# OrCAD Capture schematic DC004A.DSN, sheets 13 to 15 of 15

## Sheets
13 PAGE12 - LEVEL SHIFTERS: size B; title: ADC12DJ3200EVMCVAL (LEVEL SHIFTERS)
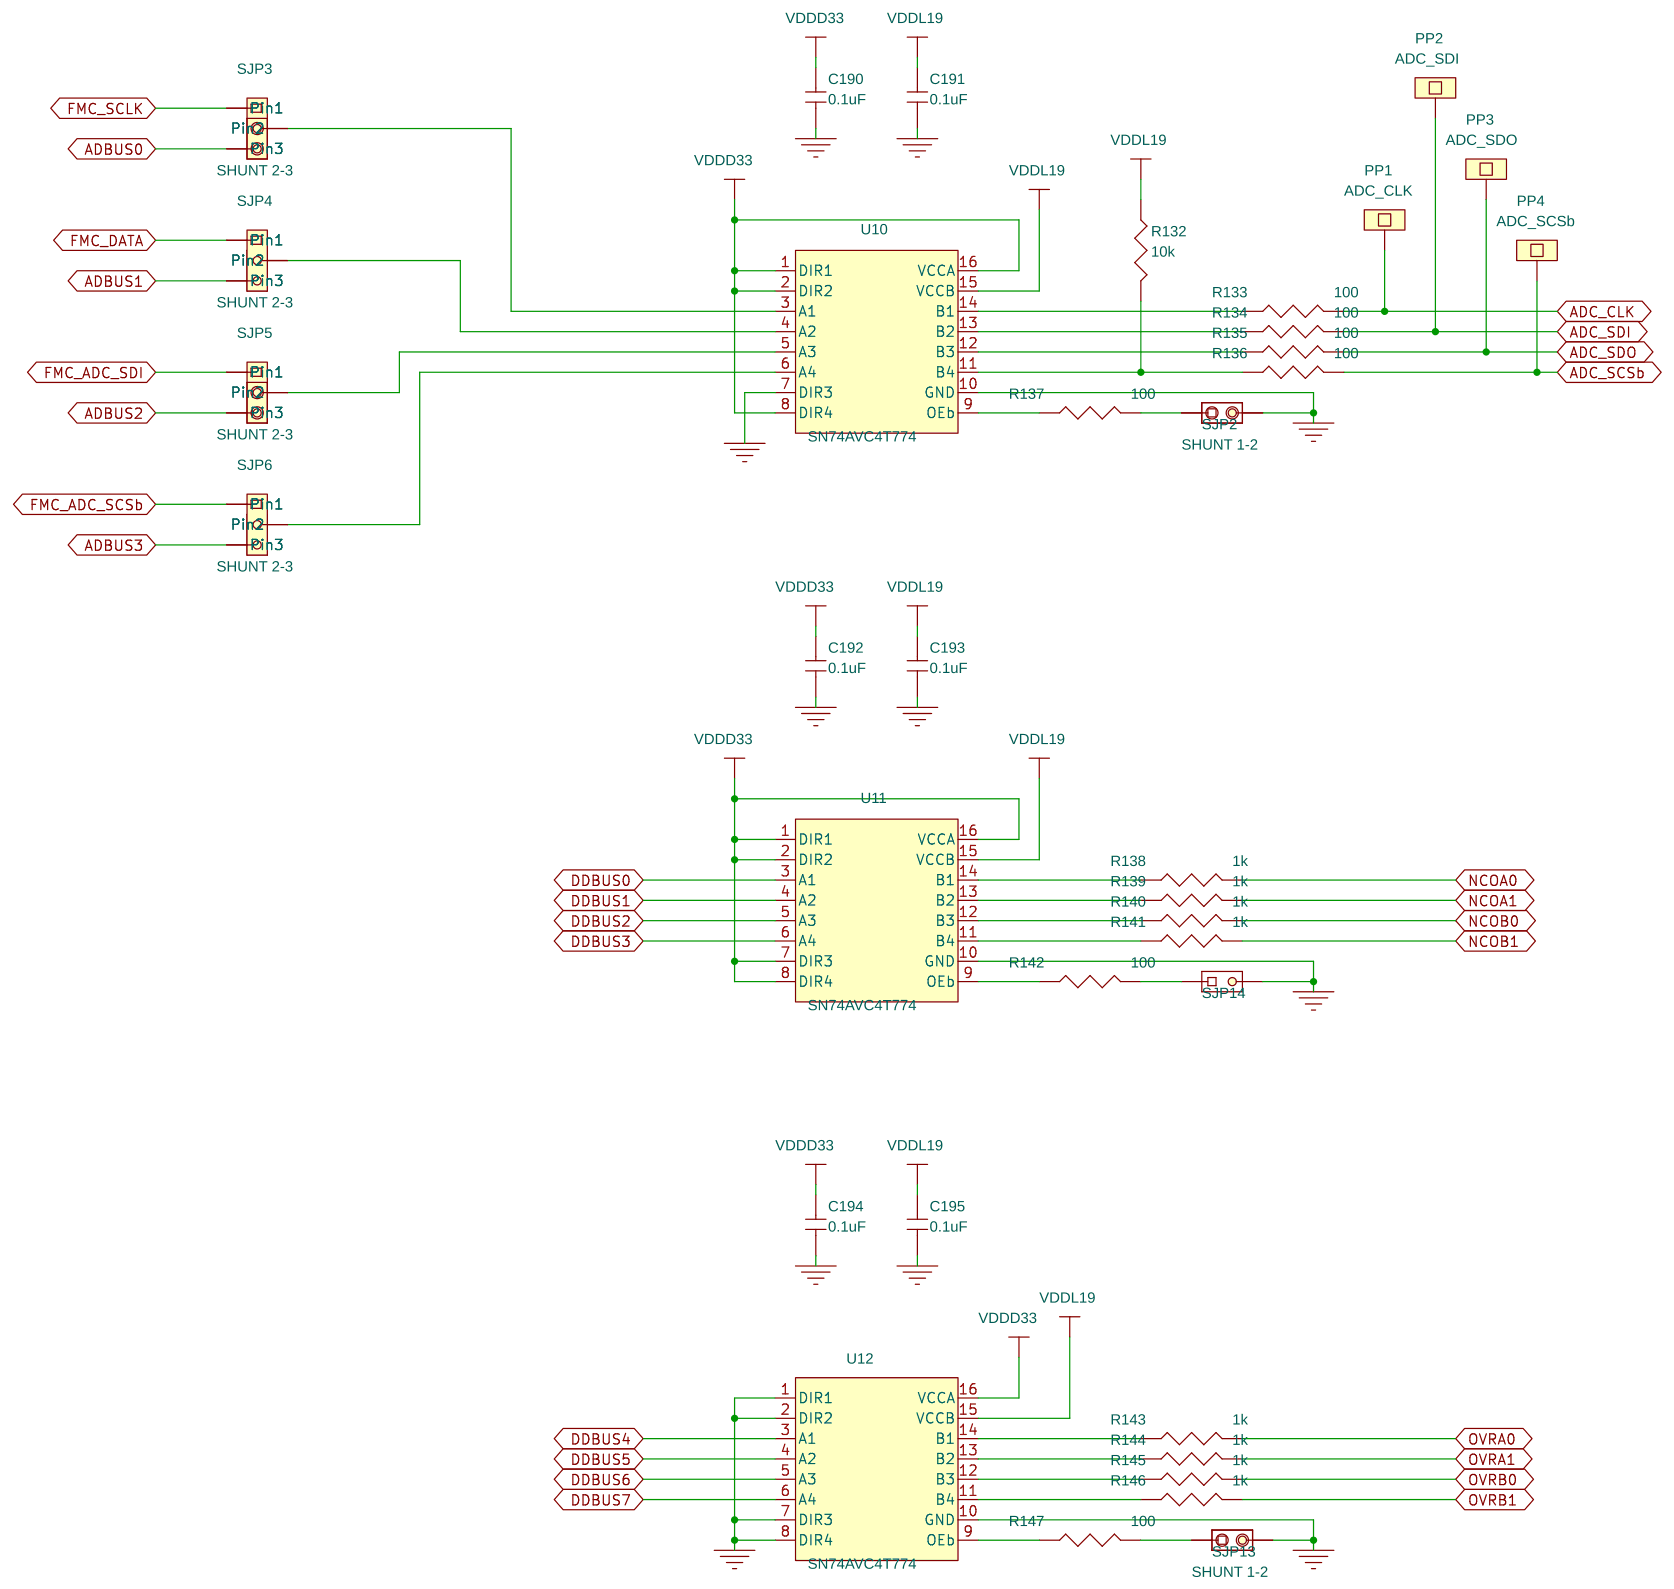
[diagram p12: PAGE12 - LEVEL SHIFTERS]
14 PAGE13 - POWER SUPPLIES: size B; title: ADC12DJ3200EVMCVAL (Power)
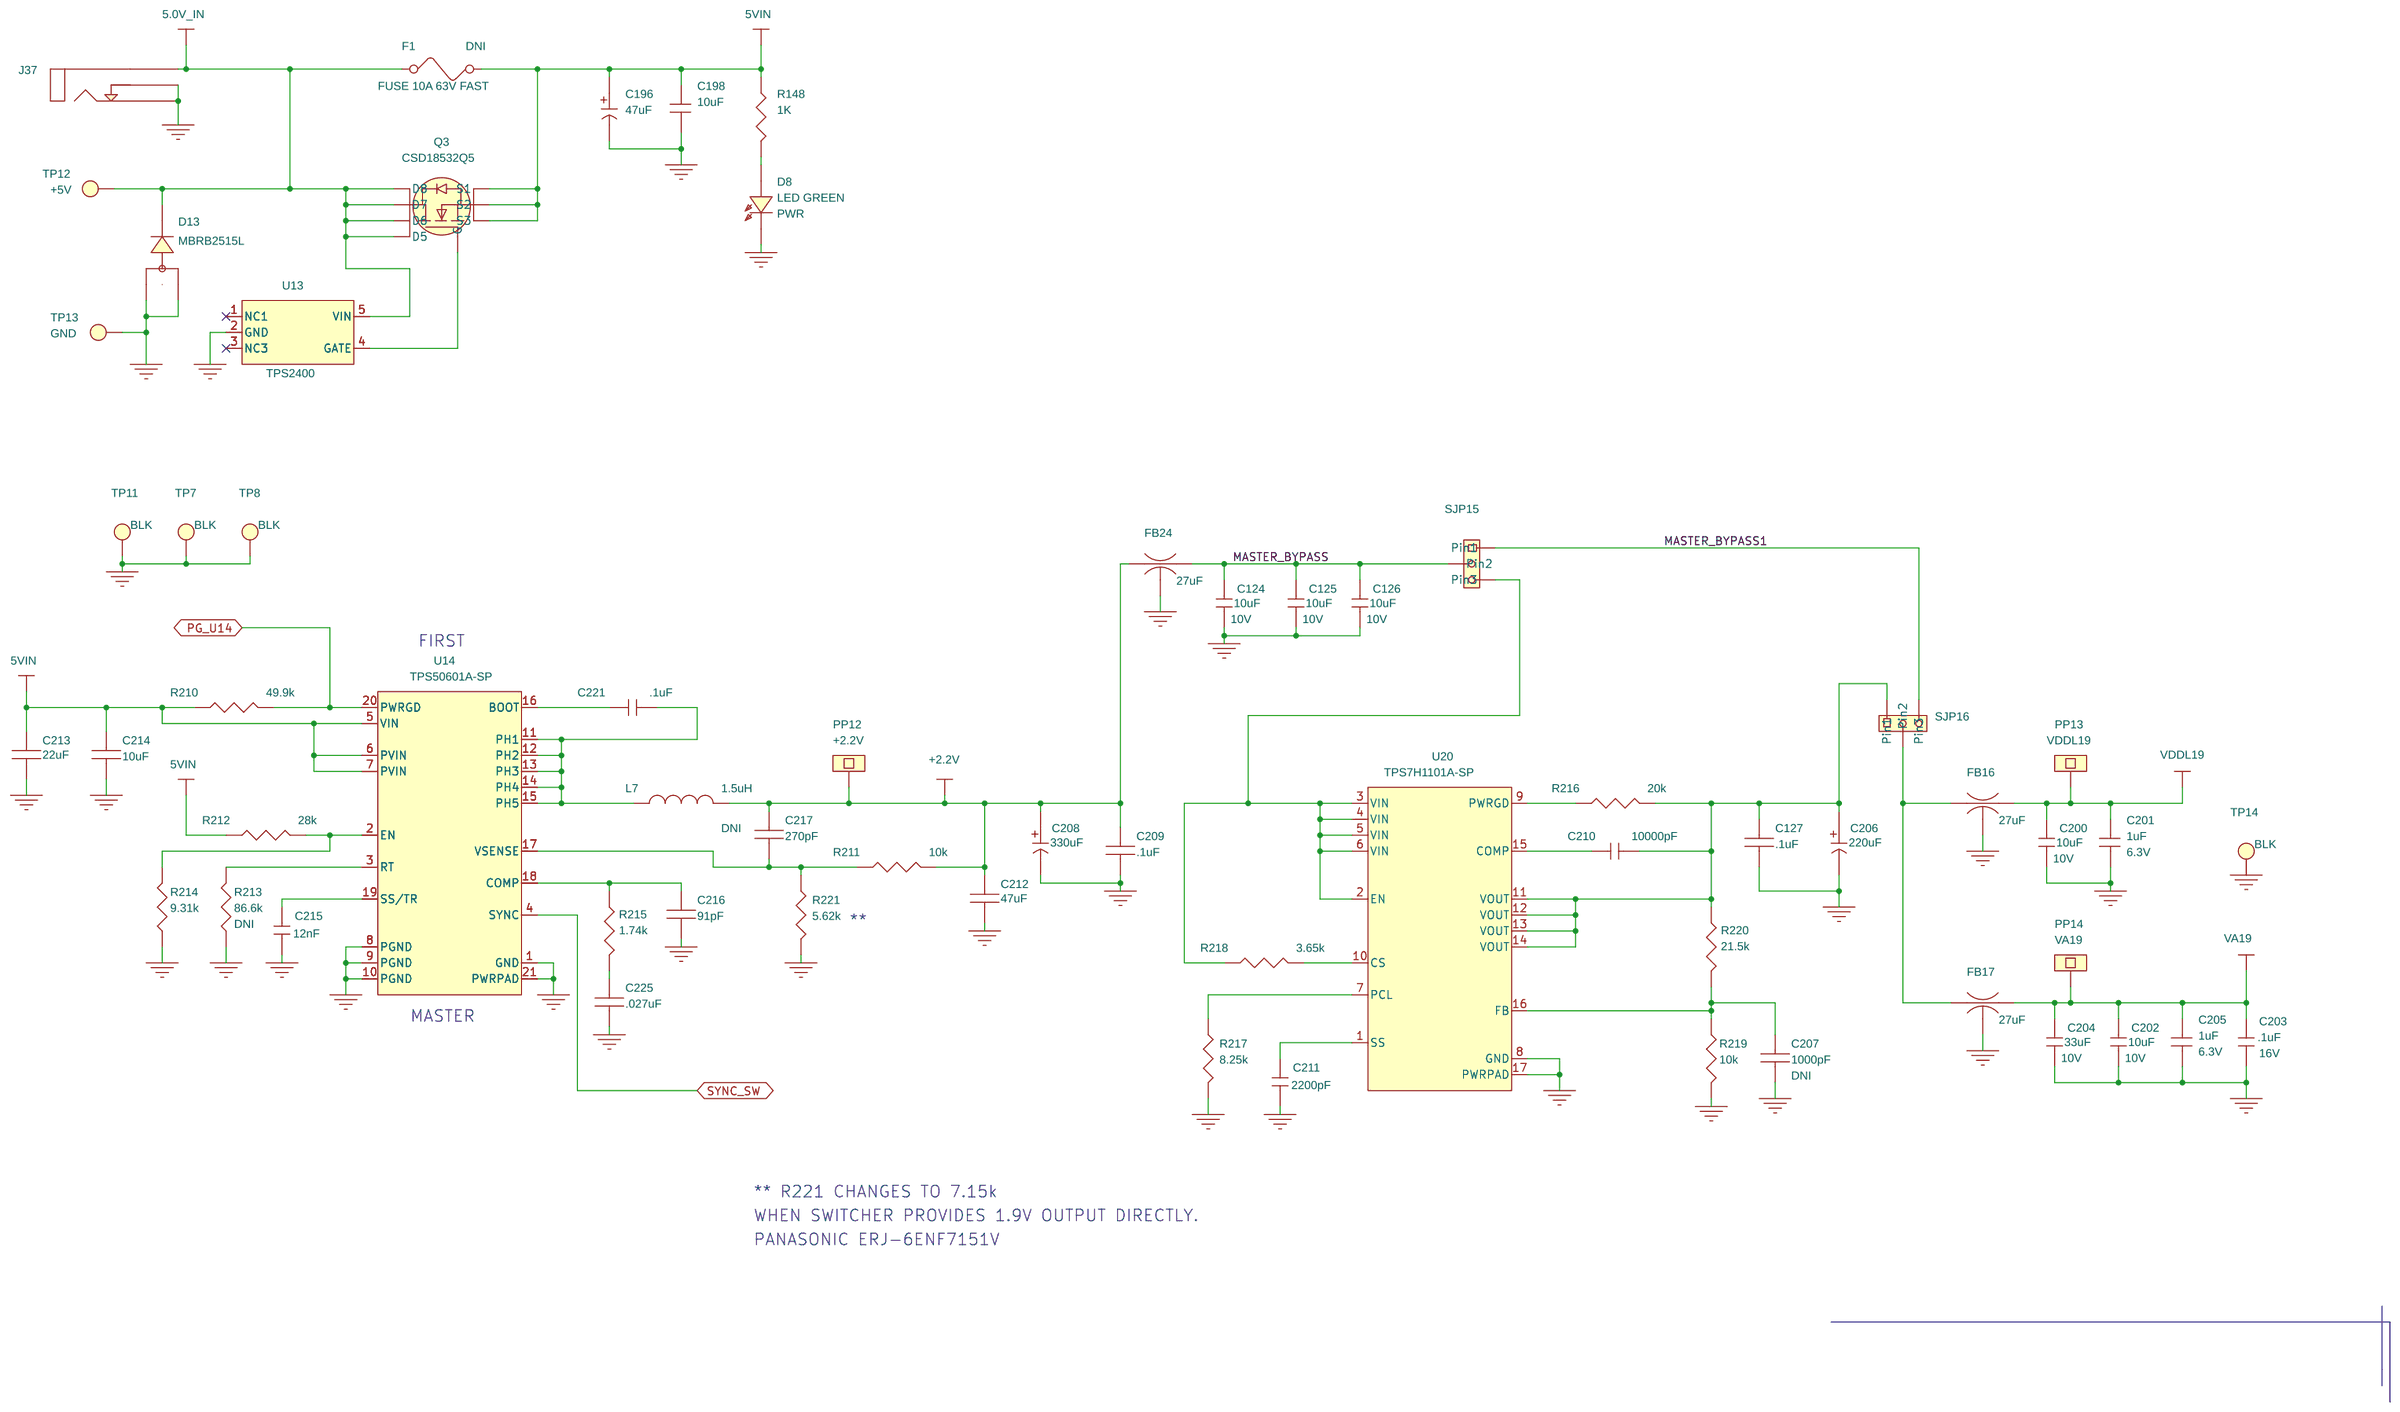
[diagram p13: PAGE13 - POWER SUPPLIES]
15 PAGE14 - POWER SUPPLIES: size B; title: ADC12DJ3200EVMCVAL (Power)
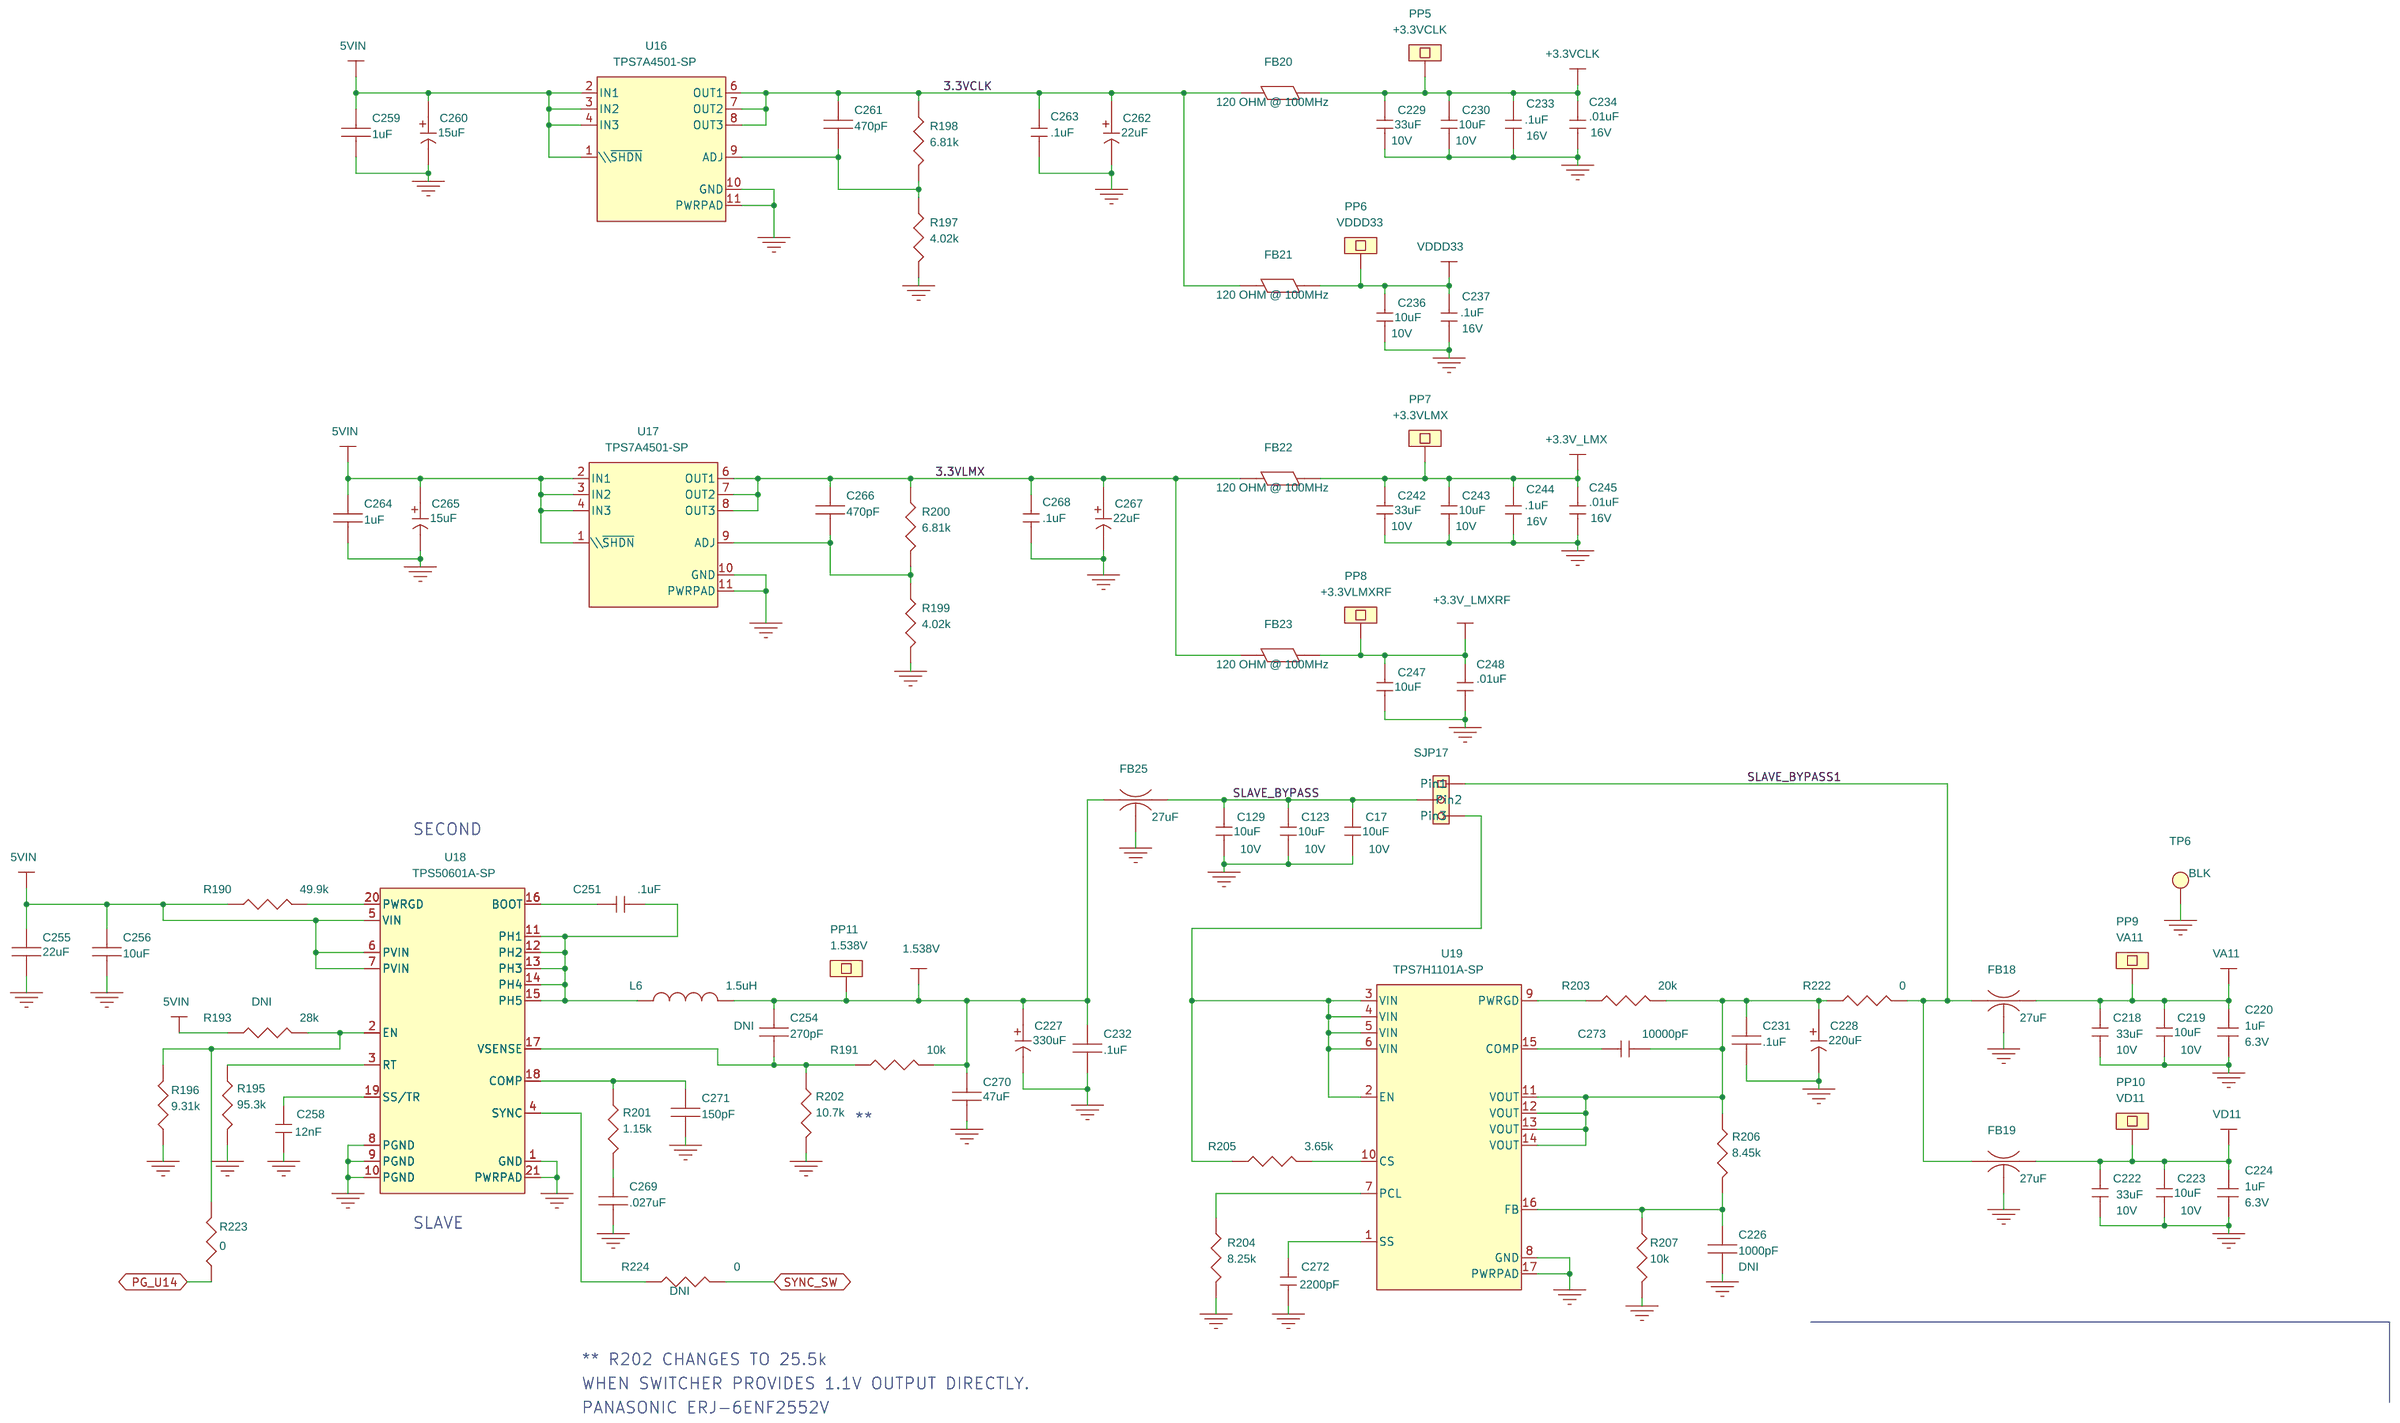
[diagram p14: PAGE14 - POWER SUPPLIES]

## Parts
sheet PAGE12 - LEVEL SHIFTERS
C190  0.1uF  [0603]
C191  0.1uF  [0603]
C192  0.1uF  [0603]
C193  0.1uF  [0603]
C194  0.1uF  [0603]
C195  0.1uF  [0603]
PP1  PROBE POINT  [PROBE_POINT_30PAD]
PP2  PROBE POINT  [PROBE_POINT_30PAD]
PP3  PROBE POINT  [PROBE_POINT_30PAD]
PP4  PROBE POINT  [PROBE_POINT_30PAD]
R132  10k  [0402]
R133  100  [0402]
R134  100  [0402]
R135  100  [0402]
R136  100  [0402]
R137  100  [0402]
R138  1k  [0402]
R139  1k  [0402]
R140  1k  [0402]
R141  1k  [0402]
R142  100  [0402]
R143  1k  [0402]
R144  1k  [0402]
R145  1k  [0402]
R146  1k  [0402]
R147  100  [0402]
SJP2  SOLDER JUMPER, 0402  [SJP2_JUMPER_0402]
SJP3  JUMPER_1X3_100  [JUMPER_SMD_3POS_0402]
SJP4  JUMPER_1X3_100  [JUMPER_SMD_3POS_0402]
SJP5  JUMPER_1X3_100  [JUMPER_SMD_3POS_0402]
SJP6  JUMPER_1X3_100  [JUMPER_SMD_3POS_0402]
SJP13  SOLDER JUMPER, 0402  [SJP2_JUMPER_0402]
SJP14  SOLDER JUMPER, 0402  [SJP2_JUMPER_0402]
U10  SN74AVC4T774  [TSSOP_16_201x177_26]
U11  SN74AVC4T774  [TSSOP_16_201x177_26]
U12  SN74AVC4T774  [TSSOP_16_201x177_26]
Z_SH-J6  SHUNT-JUMPER-0402
Z_SH-J7  SHUNT-JUMPER-0402
Z_SH-J8  SHUNT-JUMPER-0402
Z_SH-J9  SHUNT-JUMPER-0402
Z_SH-J10  SHUNT-JUMPER-0402
Z_SH-J17  SHUNT-JUMPER-0402
sheet PAGE13 - POWER SUPPLIES
C124  10uF  [0603]
C125  10uF  [0603]
C126  10uF  [0603]
C127  .1uF  [0805]
C196  47uF  [TANT_B]
C198  10uF  [0603]
C200  10uF  [0603]
C201  1uF  [0402]
C202  10uF  [0603]
C203  .1uF  [0402]
C204  33uF  [0805]
C205  1uF  [0402]
C206  220uF  [TANT_D]
C207  1000pF  [0805]
C208  330uF  [TANT_D]
C209  .1uF  [0805]
C210  10000pF  [0201]
C211  2200pF  [0201]
C212  47uF  [1206]
C213  22uF  [1206]
C214  10uF  [0805]
C215  12nF  [0201]
C216  91pF  [0805]
C217  270pF  [0805]
C221  .1uF  [0805]
C225  .027uF  [0805]
D8  LED GREEN  [LED_0805]
D13  MBRB2515L  [DIODE_MBRB2515L]
F1  FUSE 10A 63V FAST  [1206]
FB16  27uF  [1206_BEAD_NFM31P]
FB17  27uF  [1206_BEAD_NFM31P]
FB24  27uF  [1206_BEAD_NFM31P]
J37  CONN, JACK, PWR, MINI, R/A, TH  [CON_RAPC722_JACK_THVT_3]
L7  1.5uH  [IND_SM_6p7MMx6p7MM]
PP12  PROBE POINT  [PROBE_POINT_30PAD]
PP13  PROBE POINT  [PROBE_POINT_30PAD]
PP14  PROBE POINT  [PROBE_POINT_30PAD]
Q3  CSD18532Q5  [SON_Q5B_8]
R148  1K  [0402]
R210  49.9k  [0402]
R211  10k  [0402]
R212  28k  [0402]
R213  86.6k  [0402]
R214  9.31k  [0402]
R215  1.74k  [0402]
R216  20k  [0402]
R217  8.25k  [0402]
R218  3.65k  [0402]
R219  10k  [0402]
R220  21.5k  [0402]
R221  5.62k  [0805]
SJP15  JUMPER_1X3_100  [JUMPER_SMD_3POS_0805]
SJP16  JUMPER_1X3_100  [JUMPER_SMD_3POS_0805]
TP7  BLK  [TP_THVT_100_RND]
TP8  BLK  [TP_THVT_100_RND]
TP11  BLK  [TP_THVT_100_RND]
TP12  RED  [TP_THVT_125_RND_063D]
TP13  BLK  [TP_THVT_125_RND_063D]
TP14  BLK  [TP_THVT_100_RND]
U13  TPS2400  [DBV5]
U14  TPS50601A-SP  [CFP_20_300x510_50_PWRPAD]
U20  TPS7H1101A-SP  [DUAL_FLATPACK_TPS7H1101-SP]
sheet PAGE14 - POWER SUPPLIES
C17  10uF  [0603]
C123  10uF  [0603]
C129  10uF  [0603]
C218  33uF  [0805]
C219  10uF  [0603]
C220  1uF  [0402]
C222  33uF  [0805]
C223  10uF  [0603]
C224  1uF  [0402]
C226  1000pF  [0805]
C227  330uF  [TANT_D]
C228  220uF  [TANT_D]
C229  33uF  [0805]
C230  10uF  [0603]
C231  .1uF  [0805]
C232  .1uF  [0805]
C233  .1uF  [0402]
C234  .01uF  [0201]
C236  10uF  [0603]
C237  .1uF  [0402]
C242  33uF  [0805]
C243  10uF  [0603]
C244  .1uF  [0402]
C245  .01uF  [0201]
C247  10uF  [0603]
C248  .01uF  [0201]
C251  .1uF  [0805]
C254  270pF  [0805]
C255  22uF  [1206]
C256  10uF  [0805]
C258  12nF  [0201]
C259  1uF  [0805]
C260  15uF  [TANT_X]
C261  470pF  [0805]
C262  22uF  [TANT_D]
C263  .1uF  [1210]
C264  1uF  [0805]
C265  15uF  [TANT_X]
C266  470pF  [0805]
C267  22uF  [TANT_D]
C268  .1uF  [1210]
C269  .027uF  [0805]
C270  47uF  [1206]
C271  150pF  [0805]
C272  2200pF  [0201]
C273  10000pF  [0201]
FB18  27uF  [1206_BEAD_NFM31P]
FB19  27uF  [1206_BEAD_NFM31P]
FB20  120 OHM @ 100MHz  [1206]
FB21  120 OHM @ 100MHz  [1206]
FB22  120 OHM @ 100MHz  [1206]
FB23  120 OHM @ 100MHz  [1206]
FB25  27uF  [1206_BEAD_NFM31P]
L6  1.5uH  [IND_SM_6p7MMx6p7MM]
PP5  PROBE POINT  [PROBE_POINT_30PAD]
PP6  PROBE POINT  [PROBE_POINT_30PAD]
PP7  PROBE POINT  [PROBE_POINT_30PAD]
PP8  PROBE POINT  [PROBE_POINT_30PAD]
PP9  PROBE POINT  [PROBE_POINT_30PAD]
PP10  PROBE POINT  [PROBE_POINT_30PAD]
PP11  PROBE POINT  [PROBE_POINT_30PAD]
R190  49.9k  [0402]
R191  10k  [0402]
R193  28k  [0402]
R195  95.3k  [0402]
R196  9.31k  [0402]
R197  4.02k  [0805]
R198  6.81k  [0805]
R199  4.02k  [0805]
R200  6.81k  [0805]
R201  1.15k  [0402]
R202  10.7k  [0805]
R203  20k  [0402]
R204  8.25k  [0402]
R205  3.65k  [0402]
R206  8.45k  [0402]
R207  10k  [0402]
R222  0  [0805]
R223  0  [0402]
R224  0  [0402]
SJP17  JUMPER_1X3_100  [JUMPER_SMD_3POS_0805]
TP6  BLK  [TP_THVT_100_RND]
U16  TPS7A4501-SP  [CFP_10_270x276_50_PWRPAD]
U17  TPS7A4501-SP  [CFP_10_270x276_50_PWRPAD]
U18  TPS50601A-SP  [CFP_20_300x510_50_PWRPAD]
U19  TPS7H1101A-SP  [DUAL_FLATPACK_TPS7H1101-SP]

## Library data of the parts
C190-C195 = CAP_0603_0.1uF
PP1 = PROBE_POINT_0: TI_Silktext: ADC_CLK
PP2 = PROBE_POINT_0: TI_Silktext: ADC_SDI
PP3 = PROBE_POINT_0: TI_Silktext: ADC_SDO
PP4 = PROBE_POINT_0: TI_Silktext: ADC_SCSb
R132 R207 R219 = Res_0402_10k
R133-R137 R142 R147 = Res_0603_100_H: Mfr_Part_Number: ERJ-2RKF1000X
R138-R141 R143-R146 = Res_0603_1k_H: Mfr_Part_Number: ERJ-2RKF1001X
SJP2 SJP13 SJP14 = JUMPER_SMD_1X2: TI_Silktext: SHUNT 1-2
SJP3-SJP6 SJP15-SJP17 = JUMPER_SMD_3POS_0402: TI_Silktext: SHUNT 2-3
U10-U12 = SN74AVC4T774: Mfr_Name: Texas Instruments
Z_SH-J6-Z_SH-J10 Z_SH-J17 = SHUNT-JUMPER-0402
C17 C123-C126 C129 C200 C202 C219 C223 = CAP0201_0: Mfr_Name: TDK; Mfr_Part_Number: C1608X5R1A106K080AC; TOL: 20%; VOLTAGE: 10V
C127 C209 C231 C232 = CAP_0805_.1uF_25V
C196 = CAP_POL-B_0: Mfr_Name: AVX; Mfr_Part_Number: TPSB476K010R0250; TOL: 10%
C198 = CAP_NP_1: Mfr_Name: TDK; Mfr_Part_Number: C1608X5R1A106K080AC; TOL: 10%; VOLTAGE: 10V
C201 C205 C220 C224 = CAP_NP_1: Mfr_Name: YAGEO; Mfr_Part_Number: CC0402KRX7R5BB105; TOL: 10%; VOLTAGE: 6.3V
C203 C233 C237 C244 = CAP0603: Mfr_Name: MURATA; Mfr_Part_Number: GRM155R71C104KA88D; TOL: 10%; Voltage: 16V
C204 C218 C222 C229 C242 = CAP0201_0: Mfr_Name: TDK; Mfr_Part_Number: C2012X5R1A336M125AC; TOL: 20%; VOLTAGE: 10V
C206 C228 = CAP_TANT_D_220uF_6.3V
C207 C226 = CAP_0805_1000pF_25V: Mfr_Part_Number: GRM216R71E102KA01D_DNI; Note: DNI
C208 C227 = CAP_TANT_D_220uF_6.3V: Mfr_Name: KEMET; Mfr_Part_Number: T491D337K006AT; Tol: 10%
C210 C273 = CAP_0201_10000pF
C211 C272 = CAP_0201_2200pF
C212 C270 = CAP_1206_47uF: Mfr_Part_Number: GRM31CE70G476ME15L
C213 C255 = CAP_1206_2.2uF: Mfr_Part_Number: GRM31CR61A226ME19L
C214 C256 = CAP_0805_10uF_10V
C215 C258 = CAP_0201_0.1uF: Mfr_Name: MURATA; Mfr_Part_Number: GRM033C80J123KE01D
C216 = CAP_0805_91pF_50V
C217 C254 = CAP_0805_9.0pF: Mfr_Name: SAMSUNG; Mfr_Part_Number: CL21C271JBANFNC_DNI; Note: DNI
C221 C251 = CAP_0805_0.1uF_X7R_50V: Mfr_Name: KEMET; Mfr_Part_Number: C0805C104K5RACTU
C225 C269 = CAP_0805_.027uF_50V
D8 = LED_GREEN_0: Mfr_Part_Number: LTST-C170KGKT; TI_SILKTEXT: PWR
D13 = DIODE_MBRB2515L
F1 = FUSE_0: Mfr_Name: TE Connectivity; Mfr_Part_Number: 1206SFF200F/63-2_DNI; Note: DNI
FB16-FB19 FB24 FB25 = BEAD_NFM31P: Mfr_Name: Murata; Mfr_Part_Number: NFM31PC276B0J3L; Tolerance: 20%
J37 = CONN_JACK_PWR: Mfr_Name: SWITCHCRAFT; Mfr_Part_Number: RAPC722X
L6 L7 = IND_POWER_1.5uH
PP12 = PROBE_POINT_0: TI_Silktext: +2.2V
PP13 = PROBE_POINT_0: TI_Silktext: VDDL19
PP14 = PROBE_POINT_0: TI_Silktext: VA19
Q3 = CSD18532Q5B: Mfr_Name: Texas Instruments
R148 = Res_0402_1k: TOL: 1%
R210 = Res_0402_49.9k: Mfr_Part_Number: ERJ-2RKF4992X
R191 R211 = Res_0402_10k_H
R212 = Res_0402_28k_H
R213 = Res_0402_86.6k_H: Mfr_Part_Number: ERJ-2RKF8662X_DNI; Note: DNI
R196 R214 = Res_0402_9.31k_H
R215 = Res_0402_1.82k: Mfr_Part_Number: ERJ-2RKF1741X
R203 R216 = Res_0402_20K_H
R204 R217 = Res_0402_8.25: Mfr_Part_Number: CRCW04028K25FKED
R205 R218 = Res_0402_3.65K_H
R220 = Res_0402_21.5k
R221 = Res_0805_4.87k: ALTERNATE_PART_NUMBER: 7.15k, ERJ-6ENF7151V; Mfr_Name: PANASONIC; Mfr_Part_Number: ERJ-6ENF5621V
TP6-TP8 TP11 TP14 = TESTPOINT_BLK: Mfr_Name: KEYSTONE; Mfr_Part_Number: 5001
TP12 = TESTLOOP_BLACK: Mfr_Name: KEYSTONE; Mfr_Part_Number: 5010; TI_SILKTEXT: +5V
TP13 = TESTLOOP_BLACK: Mfr_Name: KEYSTONE; Mfr_Part_Number: 5011; TI_SILKTEXT: GND
U13 = TPS2400: Mfr_Name: Texas Instruments; Mfr_Part_Number: TPS2400DBVT
U14 U18 = TPS50601A-SP
U19 U20 = TPS7H1101-SP: Mfr_Part_Number: TPS7H1101AHKR/EM
C230 C236 C243 C247 = CAP0201_0: Mfr_Name: TDK; Mfr_Part_Number: C1608X5R1A106K080AC; TOL: 10%; VOLTAGE: 10V
C234 C245 C248 = CAP0402_0: Mfr_Name: YAGEO; Mfr_Part_Number: CC0201KRX7R7BB103; TOL: 10%; Voltage: 16V
C259 C264 = CAP_0805_1uF_50V
C260 C265 = CAP_TANT_X_15uF_50V
C261 C266 = CAP_0805_470pF
C262 C267 = CAP_TANT_D_22uF_25V
C263 C268 = CAP_1210_.1uF_50V
C271 = CAP_0805_130pF_50V: Mfr_Part_Number: CL21C151GBANNNC
FB20-FB23 = FERRITE_BEAD_0402_H: Isat: 500mA; Mfr_Name: MURATA; Mfr_Part_Number: BLM31PG121SN1L
PP5 = PROBE_POINT_0: TI_Silktext: +3.3VCLK
PP6 = PROBE_POINT_0: TI_Silktext: VDDD33
PP7 = PROBE_POINT_0: TI_Silktext: +3.3VLMX
PP8 = PROBE_POINT_0: TI_Silktext: +3.3VLMXRF
PP9 = PROBE_POINT_0: TI_Silktext: VA11
PP10 = PROBE_POINT_0: TI_Silktext: VD11
PP11 = PROBE_POINT_0: TI_Silktext: 1.538V
R190 = Res_0402_49.9k
R193 = Res_0402_28k_H: Mfr_Part_Number: ERJ-2RKF2802X_DNI; Note: DNI
R195 = Res_0402_95.3k
R197 R199 = Res_0805_4.02k
R198 R200 = Res_0805_6.81k
R201 = Res_0402_1.21k: Mfr_Part_Number: ERJ-2RKF1151X
R202 = Res_0402_9.76k: Mfr_Part_Number: ERJ-6ENF1072V
R206 = Res_0402_8.45k
R222 = Res_0805_Zero_H
R223 = Res_0402_Zero_H
R224 = Res_0402_Zero_H: Mfr_Part_Number: ERJ-2GE0R00X_DNI; Note: DNI
U16 U17 = TPS7A4501-SP

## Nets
1.538V: C227.1 C232.1 C254.1 C270.1 FB25.1 L6.2 PP11.1 R191.2
3.3VCLK: C261.1 C262.1 C263.1 FB20.1 FB21.1 R198.1 U16.6(OUT1) U16.7(OUT2) U16.8(OUT3)
3.3VLMX: C266.1 C267.1 C268.1 FB22.1 FB23.1 R200.1 U17.6(OUT1) U17.7(OUT2) U17.8(OUT3)
5.0V_IN: D13.4 F1.1 J37.1 Q3.5(D5) Q3.6(D6) Q3.7(D7) Q3.8(D8) TP12.1(TP) U13.5(VIN)
5VIN: C196.1 C198.1 C213.1 C214.1 C255.1 C256.1 C259.1 C260.1 C264.1 C265.1 F1.2 Q3.1(S1) Q3.2(S2) Q3.3(S3) R148.1 R190.1 R193.1 R210.1 R212.1 U14.5(VIN) U14.6(PVIN) U14.7(PVIN) U16.1(\\~{SHDN}) U16.2(IN1) U16.3(IN2) U16.4(IN3) U17.1(\\~{SHDN}) U17.2(IN1) U17.3(IN2) U17.4(IN3) U18.5(VIN) U18.6(PVIN) U18.7(PVIN)
+2.2V: C208.1 C209.1 C212.1 C217.1 FB24.1 L7.2 PP12.1 R211.2
+3.3V_LMX: C242.1 C243.1 C244.1 C245.1 FB22.2 PP7.1 ; also on sheet 6
+3.3V_LMXRF: C247.1 C248.1 FB23.2 PP8.1 ; also on sheet 6
+3.3VCLK: C229.1 C230.1 C233.1 C234.1 FB20.2 PP5.1 ; also on sheet 7 8
GND: C17.2 C123.2 C124.2 C125.2 C126.2 C127.2 C129.2 C190.2 C191.2 C192.2 C193.2 C194.2 C195.2 C196.2 C198.2 C200.2 C201.2 C202.2 C203.2 C204.2 C205.2 C206.2 C207.2 C208.2 C209.2 C211.2 C212.2 C213.2 C214.2 C215.2 C216.2 C218.2 C219.2 C220.2 C222.2 C223.2 C224.2 C225.2 C226.2 C227.2 C228.2 C229.2 C230.2 C231.2 C232.2 C233.2 C234.2 C236.2 C237.2 C242.2 C243.2 C244.2 C245.2 C247.2 C248.2 C255.2 C256.2 C258.2 C259.2 C260.2 C262.2 C263.2 C264.2 C265.2 C267.2 C268.2 C269.2 C270.2 C271.2 C272.2 D8.2(CATHODE) D13.1 D13.3 FB16.2 FB17.2 FB18.2 FB19.2 FB24.2 FB25.2 J37.2 J37.3 R195.2 R196.1 R197.2 R199.2 R202.2 R204.2 R207.2 R213.1 R214.1 R217.2 R219.2 R221.2 SJP2.2 SJP13.2 SJP14.2 TP6.1(TP) TP7.1(TP) TP8.1(TP) TP11.1(TP) TP13.1(TP) TP14.1(TP) U10.7(DIR3) U10.10(GND) U11.10(GND) U12.1(DIR1) U12.2(DIR2) U12.7(DIR3) U12.8(DIR4) U12.10(GND) U13.2(GND) U14.1(GND) U14.8(PGND) U14.9(PGND) U14.10(PGND) U14.21(PWRPAD) U16.10(GND) U16.11(PWRPAD) U17.10(GND) U17.11(PWRPAD) U18.1(GND) U18.8(PGND) U18.9(PGND) U18.10(PGND) U18.21(PWRPAD) U19.8(GND) U19.17(PWRPAD) U20.8(GND) U20.17(PWRPAD) ; also on sheet 1 3 4 5 6 7 8 9 10 11 12
VDDD33: C190.1 C192.1 C194.1 C236.1 C237.1 FB21.2 PP6.1 U10.1(DIR1) U10.2(DIR2) U10.8(DIR4) U10.16(VCCA) U11.1(DIR1) U11.2(DIR2) U11.7(DIR3) U11.8(DIR4) U11.16(VCCA) U12.16(VCCA) ; also on sheet 4 12
VDDL19: C191.1 C193.1 C195.1 C200.1 C201.1 FB16.3 PP13.1 R132.1 U10.15(VCCB) U11.15(VCCB) U12.15(VCCB)
2: D13.2
ADBUS0: SJP3.3(Pin3) ; also on sheet 12
ADBUS1: SJP4.3(Pin3) ; also on sheet 12
ADBUS2: SJP5.3(Pin3) ; also on sheet 12
ADBUS3: SJP6.3(Pin3) ; also on sheet 12
ADC_CLK: PP1.1 R133.2 ; also on sheet 4
ADC_SCSb: PP4.1 R136.2 ; also on sheet 4
ADC_SDI: PP2.1 R134.2 ; also on sheet 4
ADC_SDO: PP3.1 R135.2 ; also on sheet 4
DDBUS0: U11.3(A1) ; also on sheet 12
DDBUS1: U11.4(A2) ; also on sheet 12
DDBUS2: U11.5(A3) ; also on sheet 12
DDBUS3: U11.6(A4) ; also on sheet 12
DDBUS4: U12.3(A1) ; also on sheet 10 12
DDBUS5: U12.4(A2) ; also on sheet 12
DDBUS6: U12.5(A3) ; also on sheet 10 12
DDBUS7: U12.6(A4) ; also on sheet 12
FMC_ADC_SCSb: SJP6.1(Pin1) ; also on sheet 10
FMC_ADC_SDI: SJP5.1(Pin1) ; also on sheet 10
FMC_DATA: SJP4.1(Pin1) ; also on sheet 10 12
FMC_SCLK: SJP3.1(Pin1) ; also on sheet 10 12
MASTER_BYPASS: C124.1 C125.1 C126.1 FB24.3 SJP15.2(Pin2)
MASTER_BYPASS1: SJP15.1(Pin1) SJP16.3(Pin3)
NCOA0: R138.2 ; also on sheet 3
NCOA1: R139.2 ; also on sheet 3
NCOB0: R140.2 ; also on sheet 3
NCOB1: R141.2 ; also on sheet 3
OVRA0: R143.2 ; also on sheet 4 10
OVRA1: R144.2 ; also on sheet 4
OVRB0: R145.2 ; also on sheet 4 9
OVRB1: R146.2 ; also on sheet 4
PG_U14: R210.2 R223.1 U14.20(PWRGD)
SLAVE_BYPASS: C17.1 C123.1 C129.1 FB25.3 SJP17.2(Pin2)
SLAVE_BYPASS1: FB18.1 FB19.1 R222.2 SJP17.1(Pin1)
SYNC_SW: R224.2 U14.4(SYNC)
VA11: C218.1 C219.1 C220.1 FB18.3 PP9.1 ; also on sheet 5
VA19: C202.1 C203.1 C204.1 C205.1 FB17.3 PP14.1 ; also on sheet 3 4 5
VD11: C222.1 C223.1 C224.1 FB19.3 PP10.1 ; also on sheet 5
N18340257: D8.1(ANODE) R148.2
N19955835: Q3.4(G) U13.4(GATE)
N20475697: R138.1 U11.14(B1)
N20475701: R139.1 U11.13(B2)
N20475713: R140.1 U11.12(B3)
N20475725: R141.1 U11.11(B4)
N20475883: R142.1 U11.9(OEb)
N20476138: R142.2 SJP14.1
N20477206: R133.1 U10.14(B1)
N20477210: R134.1 U10.13(B2)
N20477222: R135.1 U10.12(B3)
N20477234: R132.2 R136.1 U10.11(B4)
N20477346: SJP3.2(Pin2) U10.3(A1)
N20477348: SJP4.2(Pin2) U10.4(A2)
N20477350: SJP5.2(Pin2) U10.5(A3)
N20477352: SJP6.2(Pin2) U10.6(A4)
N20477392: R137.1 U10.9(OEb)
N20479286: R143.1 U12.14(B1)
N20479288: R144.1 U12.13(B2)
N20479290: R145.1 U12.12(B3)
N20479292: R146.1 U12.11(B4)
N20479340: R147.1 U12.9(OEb)
N20479396: R147.2 SJP13.1
N20759391: C261.2 R197.1 R198.2 U16.9(ADJ)
N20760406: C266.2 R199.1 R200.2 U17.9(ADJ)
N20770678: R205.1 SJP17.3(Pin3) U19.2(EN) U19.3(VIN) U19.4(VIN) U19.5(VIN) U19.6(VIN)
N20770696: C272.1 U19.1(SS)
N20770708: C273.1 U19.15(COMP)
N20770710: C228.1 C231.1 C273.2 R203.2 R206.1 R222.1 U19.11(VOUT) U19.12(VOUT) U19.13(VOUT) U19.14(VOUT)
N20770722: R203.1 U19.9(PWRGD)
N20770740: R204.1 U19.7(PCL)
N20770762: R205.2 U19.10(CS)
N20770834: C226.1 R206.2 R207.1 U19.16(FB)
N20771140: C254.2 R191.1 R202.1 U18.17(VSENSE)
N20771180: C269.1 R201.2
N20771182: C271.1 R201.1 U18.18(COMP)
N20771289: R190.2 U18.20(PWRGD)
N20771323: R193.2 R196.2 R223.2 U18.2(EN)
N20771329: R195.1 U18.3(RT)
N20771355: C258.1 U18.19(SS/TR)
N20771381: C251.1 U18.16(BOOT)
N20771385: C251.2 L6.1 U18.11(PH1) U18.12(PH2) U18.13(PH3) U18.14(PH4) U18.15(PH5)
N20772111: C217.2 R211.1 R221.1 U14.17(VSENSE)
N20772147: C225.1 R215.2
N20772149: C216.1 R215.1 U14.18(COMP)
N20772286: R212.2 R214.2 U14.2(EN)
N20772300: R213.2 U14.3(RT)
N20772322: C215.1 U14.19(SS/TR)
N20772348: C221.1 U14.16(BOOT)
N20772352: C221.2 L7.1 U14.11(PH1) U14.12(PH2) U14.13(PH3) U14.14(PH4) U14.15(PH5)
N20774965: R218.1 SJP15.3(Pin3) U20.2(EN) U20.3(VIN) U20.4(VIN) U20.5(VIN) U20.6(VIN)
N20775006: C211.1 U20.1(SS)
N20775018: C210.1 U20.15(COMP)
N20775020: C127.1 C206.1 C210.2 R216.2 R220.1 SJP16.1(Pin1) U20.11(VOUT) U20.12(VOUT) U20.13(VOUT) U20.14(VOUT)
N20775032: R216.1 U20.9(PWRGD)
N20775050: R217.1 U20.7(PCL)
N20775064: R218.2 U20.10(CS)
N20775144: C207.1 R219.1 R220.2 U20.16(FB)
N20776452: FB16.1 FB17.1 SJP16.2(Pin2)
N20814533: R224.1 U18.4(SYNC)
N20965250: R137.2 SJP2.1

Not connected (* = marked no-connect by the designer): U13 1(NC1)* 3(NC3)*

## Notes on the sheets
sheet 14
- FIRST
- **
- MASTER
- ** R221 CHANGES TO 7.15k
- WHEN SWITCHER PROVIDES 1.9V OUTPUT DIRECTLY.
- PANASONIC ERJ-6ENF7151V
sheet 15
- SECOND
- **
- SLAVE
- ** R202 CHANGES TO 25.5k
- WHEN SWITCHER PROVIDES 1.1V OUTPUT DIRECTLY.
- PANASONIC ERJ-6ENF2552V
